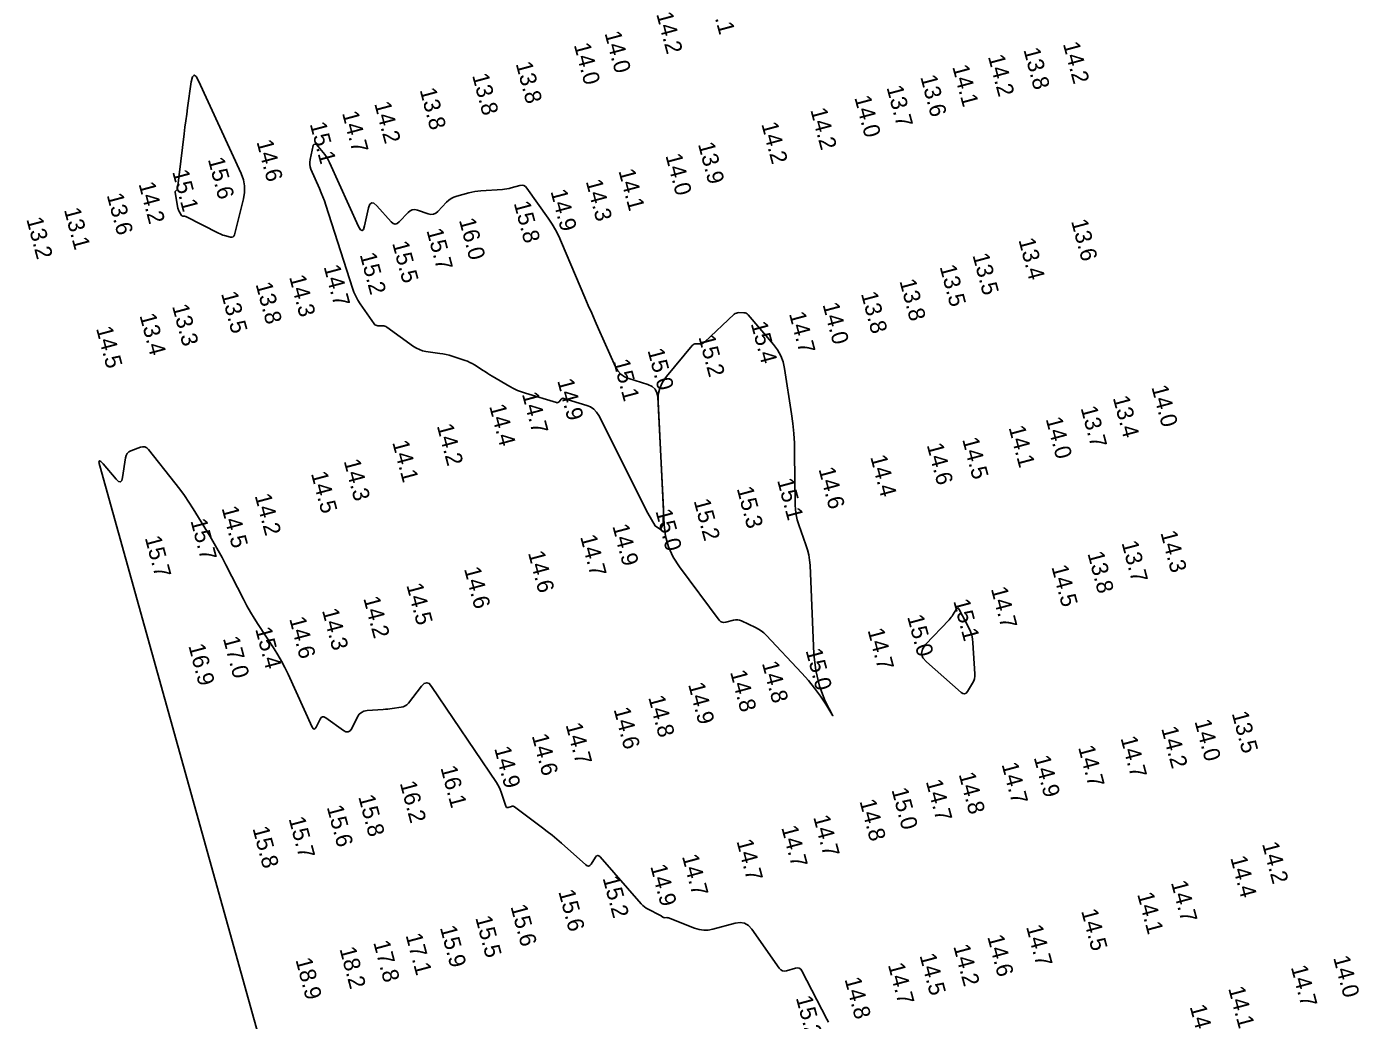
# Model space of a CAD drawing. Extents: x 988130 to 1132882, y 654656 to 841453.
# Drawn here: x 1052599.8 to 1053005.8, y 747871.9 to 748174.6 of the extents above; entities that cross this region are included whole.
import ezdxf

# ---------------------------------------------------------------- set-up
doc = ezdxf.new("R2010")
doc.units = 0
doc.layers.add('V-TOPO-MAJR', color=7, linetype='Continuous')
doc.layers.add('V-TOPO-SOUN', color=7, linetype='Continuous')

msp = doc.modelspace()

# ---------------------------------------------------------------- linework, layer by layer
at = {"layer": 'V-TOPO-MAJR'}
for points in [[(1052645.06, 748124.32), (1052645.11, 748124.42), (1052645.19, 748124.52), (1052645.55, 748124.87), (1052645.63, 748124.97), (1052645.69, 748125.07), (1052645.73, 748125.18), (1052645.76, 748125.3), (1052647.76, 748141.94), (1052648, 748143.92), (1052648.25, 748145.9), (1052648.52, 748147.87), (1052648.8, 748149.85), (1052649.93, 748157.75), (1052650.28, 748159.25), (1052650.77, 748159.81), (1052651.39, 748159.42), (1052652.16, 748158.08), (1052665.14, 748129.82), (1052665.83, 748127.95), (1052666.17, 748126.04), (1052666.18, 748124.1), (1052665.84, 748122.13), (1052663.05, 748111.14), (1052662.88, 748110.75), (1052662.64, 748110.5), (1052662.31, 748110.41), (1052661.89, 748110.46), (1052660.04, 748110.96), (1052659.58, 748111.09), (1052659.13, 748111.25), (1052658.69, 748111.43), (1052658.26, 748111.64), (1052648.24, 748116.7), (1052648.13, 748116.75), (1052648.03, 748116.79), (1052647.91, 748116.81), (1052647.8, 748116.82), (1052647.33, 748116.84), (1052647.22, 748116.86), (1052647.13, 748116.9), (1052647.04, 748116.96), (1052646.98, 748117.05), (1052646.25, 748118.25), (1052646.12, 748118.49), (1052646.01, 748118.73), (1052645.93, 748118.99), (1052645.87, 748119.25), (1052645.05, 748124.09), (1052645.04, 748124.21)], [(1052687.15, 748138.6), (1052687.22, 748138.66), (1052687.32, 748138.7), (1052687.74, 748138.81), (1052687.84, 748138.83), (1052687.93, 748138.81), (1052688.02, 748138.77), (1052688.09, 748138.7), (1052690.59, 748135.59), (1052691.01, 748135.03), (1052691.39, 748134.45), (1052691.74, 748133.84), (1052692.05, 748133.21), (1052700.91, 748113.68), (1052701.46, 748112.73), (1052701.94, 748112.44), (1052702.36, 748112.82), (1052702.7, 748113.86), (1052703.95, 748119.39), (1052704.34, 748120.46), (1052704.88, 748120.92), (1052705.58, 748120.77), (1052706.43, 748120.02), (1052710.77, 748115.12), (1052711.4, 748114.59), (1052712.03, 748114.41), (1052712.66, 748114.58), (1052713.3, 748115.1), (1052715.95, 748117.97), (1052716.57, 748118.5), (1052717.26, 748118.8), (1052718, 748118.86), (1052718.81, 748118.7), (1052722.14, 748117.56), (1052722.94, 748117.4), (1052723.69, 748117.46), (1052724.38, 748117.75), (1052725.02, 748118.26), (1052727.72, 748121.06), (1052728.4, 748121.68), (1052729.15, 748122.2), (1052729.96, 748122.61), (1052730.84, 748122.91), (1052734.47, 748123.92), (1052735.38, 748124.15), (1052736.3, 748124.33), (1052737.23, 748124.46), (1052738.17, 748124.55), (1052744.72, 748125.01), (1052745.4, 748125.08), (1052746.08, 748125.17), (1052746.75, 748125.3), (1052747.42, 748125.46), (1052750.07, 748126.18), (1052750.7, 748126.26), (1052751.27, 748126.16), (1052751.76, 748125.88), (1052752.19, 748125.41), (1052758.68, 748116.19), (1052759.84, 748114.44), (1052760.91, 748112.63), (1052761.88, 748110.77), (1052762.75, 748108.86), (1052769.87, 748092.06), (1052770.89, 748089.67), (1052771.92, 748087.28), (1052772.97, 748084.89), (1052774.03, 748082.51), (1052779.18, 748070.99), (1052779.9, 748069.73), (1052780.82, 748068.7), (1052781.95, 748067.91), (1052783.28, 748067.35), (1052789.03, 748065.58), (1052790.3, 748065), (1052791.23, 748064.16), (1052791.81, 748063.05), (1052792.06, 748061.68), (1052793.75, 748027.64), (1052793.67, 748023.09), (1052792.85, 748021.36), (1052791.29, 748022.46), (1052788.99, 748026.39), (1052774.1, 748056.09), (1052773.43, 748057.16), (1052772.59, 748058.04), (1052771.59, 748058.71), (1052770.43, 748059.19), (1052763.41, 748061.33), (1052763.18, 748061.37), (1052762.97, 748061.34), (1052762.78, 748061.25), (1052762.62, 748061.09), (1052761.99, 748060.31), (1052761.82, 748060.15), (1052761.64, 748060.05), (1052761.43, 748060.02), (1052761.2, 748060.06), (1052751.73, 748062.88), (1052750.49, 748063.29), (1052749.29, 748063.77), (1052748.11, 748064.33), (1052746.97, 748064.96), (1052741.6, 748068.14), (1052740.91, 748068.55), (1052740.23, 748068.96), (1052739.55, 748069.39), (1052738.88, 748069.81), (1052736.2, 748071.54), (1052735.52, 748071.95), (1052734.81, 748072.31), (1052734.09, 748072.63), (1052733.34, 748072.9), (1052729.38, 748074.19), (1052728.46, 748074.46), (1052727.54, 748074.7), (1052726.6, 748074.9), (1052725.66, 748075.05), (1052721.4, 748075.66), (1052720.4, 748075.87), (1052719.44, 748076.18), (1052718.53, 748076.62), (1052717.67, 748077.16), (1052709.52, 748083), (1052709.22, 748083.19), (1052708.9, 748083.32), (1052708.57, 748083.4), (1052708.21, 748083.43), (1052706.76, 748083.45), (1052706.42, 748083.49), (1052706.12, 748083.6), (1052705.85, 748083.79), (1052705.63, 748084.05), (1052701.39, 748090.14), (1052700.66, 748091.28), (1052700.02, 748092.46), (1052699.47, 748093.69), (1052699.01, 748094.96), (1052690.89, 748120.24), (1052690.46, 748121.51), (1052690, 748122.76), (1052689.51, 748124), (1052688.99, 748125.23), (1052686.39, 748131.15), (1052686.14, 748131.87), (1052686, 748132.6), (1052685.99, 748133.34), (1052686.1, 748134.09), (1052687.06, 748138.42), (1052687.09, 748138.52)], [(1052833.48, 748050.66), (1052833.67, 748047.65), (1052833.75, 748044.64), (1052833.89, 748029.01), (1052833.97, 748027.42), (1052834.19, 748025.85), (1052834.53, 748024.3), (1052835.01, 748022.77), (1052837.2, 748016.73), (1052837.68, 748015.2), (1052838.05, 748013.66), (1052838.3, 748012.08), (1052838.43, 748010.49), (1052839.63, 747983.37), (1052840.16, 747978.41), (1052841.3, 747973.63), (1052843.04, 747969.05), (1052845.39, 747964.65), (1052843.22, 747968.17), (1052841.59, 747970.67), (1052839.84, 747973.08), (1052837.97, 747975.39), (1052835.99, 747977.62), (1052825.09, 747989.21), (1052824.37, 747989.91), (1052823.59, 747990.53), (1052822.76, 747991.08), (1052821.87, 747991.55), (1052817.51, 747993.6), (1052816.94, 747993.81), (1052816.36, 747993.92), (1052815.76, 747993.91), (1052815.16, 747993.8), (1052812.74, 747993.12), (1052812.16, 747993.03), (1052811.64, 747993.12), (1052811.18, 747993.37), (1052810.77, 747993.79), (1052798.64, 748009.98), (1052796.73, 748012.93), (1052795.33, 748016.07), (1052794.41, 748019.38), (1052793.99, 748022.86), (1052792.12, 748060.37), (1052792.2, 748062.47), (1052792.66, 748064.44), (1052793.48, 748066.29), (1052794.68, 748068.01), (1052802.57, 748077.44), (1052802.8, 748077.67), (1052803.07, 748077.84), (1052803.37, 748077.94), (1052803.7, 748077.97), (1052805.07, 748077.98), (1052805.41, 748078.01), (1052805.72, 748078.1), (1052806, 748078.24), (1052806.27, 748078.45), (1052815.37, 748086.94), (1052815.67, 748087.17), (1052816, 748087.34), (1052816.35, 748087.43), (1052816.73, 748087.46), (1052818.3, 748087.44), (1052818.68, 748087.39), (1052819.02, 748087.28), (1052819.33, 748087.09), (1052819.6, 748086.83), (1052827.3, 748077.78), (1052828.53, 748076.12), (1052829.51, 748074.33), (1052830.22, 748072.42), (1052830.67, 748070.4), (1052832.78, 748056.65), (1052833.18, 748053.66)], [(1052883.44, 747997.43), (1052883.2, 747997.33), (1052882.95, 747997.03), (1052881.96, 747995.42), (1052881.7, 747995.02), (1052881.42, 747994.64), (1052881.12, 747994.27), (1052880.8, 747993.92), (1052873.63, 747986.32), (1052872.67, 747984.96), (1052872.39, 747983.62), (1052872.79, 747982.32), (1052873.88, 747981.05), (1052884.49, 747971.74), (1052885.03, 747971.39), (1052885.53, 747971.32), (1052885.99, 747971.53), (1052886.4, 747972.04), (1052887.97, 747974.61), (1052888.3, 747975.27), (1052888.53, 747975.95), (1052888.65, 747976.67), (1052888.66, 747977.4), (1052888.08, 747986.86), (1052887.95, 747988.05), (1052887.69, 747989.2), (1052887.31, 747990.32), (1052886.81, 747991.41), (1052883.89, 747997), (1052883.67, 747997.32)]]:
    msp.add_lwpolyline(points, close=True, dxfattribs=at)
msp.add_lwpolyline([(1052844.1, 747871.35), (1052843.54, 747872.24), (1052835.99, 747886.95), (1052835.62, 747887.48), (1052835.16, 747887.8), (1052834.61, 747887.9), (1052833.97, 747887.8), (1052831.24, 747886.97), (1052830.59, 747886.87), (1052830.01, 747886.96), (1052829.5, 747887.24), (1052829.06, 747887.73), (1052820.71, 747899.66), (1052819.67, 747900.79), (1052818.48, 747901.48), (1052817.13, 747901.71), (1052815.61, 747901.49), (1052808.87, 747899.62), (1052807.45, 747899.34), (1052806.05, 747899.3), (1052804.66, 747899.49), (1052803.29, 747899.91), (1052795.34, 747903.05), (1052795.2, 747903.1), (1052795.06, 747903.13), (1052794.91, 747903.15), (1052794.76, 747903.16), (1052794.14, 747903.14), (1052794, 747903.15), (1052793.87, 747903.18), (1052793.74, 747903.23), (1052793.63, 747903.3), (1052793.16, 747903.63), (1052793.05, 747903.71), (1052792.93, 747903.78), (1052792.8, 747903.85), (1052792.68, 747903.92), (1052789.17, 747905.69), (1052788.56, 747906.03), (1052788, 747906.43), (1052787.48, 747906.88), (1052786.99, 747907.38), (1052774.54, 747921.67), (1052774.14, 747922.02), (1052773.76, 747922.11), (1052773.4, 747921.96), (1052773.05, 747921.56), (1052771.71, 747919.45), (1052771.36, 747919.04), (1052770.97, 747918.87), (1052770.55, 747918.93), (1052770.1, 747919.23), (1052762.67, 747925.84), (1052761.27, 747927.06), (1052759.84, 747928.25), (1052758.39, 747929.41), (1052756.92, 747930.54), (1052748.43, 747936.9), (1052748.21, 747937.03), (1052747.97, 747937.1), (1052747.73, 747937.12), (1052747.47, 747937.06), (1052746.43, 747936.74), (1052746.19, 747936.7), (1052746, 747936.75), (1052745.85, 747936.88), (1052745.74, 747937.1), (1052744.35, 747941.37), (1052744.07, 747942.16), (1052743.73, 747942.92), (1052743.34, 747943.65), (1052742.9, 747944.36), (1052723.16, 747973.6), (1052722.42, 747974.43), (1052721.65, 747974.72), (1052720.87, 747974.48), (1052720.07, 747973.7), (1052716.06, 747968.52), (1052715.61, 747968.03), (1052715.09, 747967.65), (1052714.51, 747967.39), (1052713.86, 747967.24), (1052711.13, 747966.85), (1052710.45, 747966.76), (1052709.77, 747966.68), (1052709.08, 747966.61), (1052708.39, 747966.56), (1052703.46, 747966.23), (1052702.53, 747966.06), (1052701.75, 747965.69), (1052701.09, 747965.11), (1052700.58, 747964.32), (1052698.79, 747960.76), (1052698.3, 747960.05), (1052697.72, 747959.71), (1052697.04, 747959.74), (1052696.28, 747960.14), (1052690.87, 747964.06), (1052690.35, 747964.33), (1052689.89, 747964.35), (1052689.49, 747964.12), (1052689.15, 747963.64), (1052687.94, 747961.2), (1052687.63, 747960.74), (1052687.34, 747960.6), (1052687.05, 747960.75), (1052686.76, 747961.22), (1052679.4, 747977.34), (1052678.45, 747979.33), (1052677.42, 747981.28), (1052676.31, 747983.2), (1052675.13, 747985.07), (1052670.27, 747992.47), (1052669.08, 747994.34), (1052667.94, 747996.23), (1052666.85, 747998.16), (1052665.82, 748000.12), (1052660.43, 748010.66), (1052659.29, 748012.84), (1052658.11, 748015), (1052656.89, 748017.13), (1052655.63, 748019.24), (1052650.45, 748027.71), (1052649.16, 748029.75), (1052647.81, 748031.75), (1052646.39, 748033.71), (1052644.92, 748035.62), (1052636.84, 748045.77), (1052636.33, 748046.26), (1052635.76, 748046.54), (1052635.12, 748046.59), (1052634.43, 748046.43), (1052631.54, 748045.34), (1052630.89, 748045.01), (1052630.39, 748044.55), (1052630.05, 748043.97), (1052629.87, 748043.27), (1052629, 748037.27), (1052628.74, 748036.29), (1052628.32, 748035.87), (1052627.75, 748036.01), (1052627.01, 748036.7), (1052623.1, 748041.36), (1052622.34, 748042.15), (1052621.91, 748042.32), (1052621.8, 748041.87), (1052622.03, 748040.8), (1052727.97, 747660.65)], dxfattribs=at)

# ---------------------------------------------------------------- texts
at = {"layer": 'V-TOPO-SOUN'}
for s, p in [('14.1 ', (1052807.53, 748184.38)), ('14.2 ', (1052791.55, 748178.44)), ('14.0 ', (1052766.45, 748169.02)), ('14.0 ', (1052775.8, 748172.58)), ('14.2 ', (1052915.46, 748169.34)), ('14.2 ', (1052892.62, 748165.46)), ('13.8 ', (1052903.43, 748167.55)), ('13.8 ', (1052748.74, 748163.29)), ('14.1 ', (1052881.75, 748162.36)), ('13.8 ', (1052735.46, 748159.73)), ('13.6 ', (1052872.01, 748159.26)), ('13.8 ', (1052719.48, 748155.3)), ('14.0 ', (1052851.92, 748152.97)), ('13.7 ', (1052861.71, 748156.06)), ('14.2 ', (1052705.64, 748151.14)), ('14.2 ', (1052838.51, 748149.21)), ('15.1 ', (1052685.99, 748144.93)), ('14.7 ', (1052695.82, 748148.26)), ('14.2 ', (1052823.57, 748144.92)), ('14.6 ', (1052669.76, 748139.51)), ('13.9 ', (1052804.27, 748138.77)), ('15.6 ', (1052654.94, 748134.16)), ('14.0 ', (1052794.35, 748135.3)), ('15.1 ', (1052644.08, 748130.4)), ('14.1 ', (1052780.04, 748130.65)), ('14.2 ', (1052633.83, 748126.67)), ('14.9 ', (1052759.33, 748124.41)), ('14.3 ', (1052770.08, 748127.45)), ('13.6 ', (1052624.13, 748123.25)), ('15.8 ', (1052748.14, 748120.81)), ('13.1 ', (1052611.1, 748118.8)), ('13.2 ', (1052599.63, 748115.92)), ('15.7 ', (1052721.54, 748112.5)), ('16.0 ', (1052731.44, 748115.66)), ('13.6 ', (1052917.95, 748115.3)), ('15.5 ', (1052711.1, 748108.63)), ('13.4 ', (1052901.91, 748109.59)), ('15.2 ', (1052701.22, 748105.12)), ('13.5 ', (1052887.9, 748104.95)), ('14.7 ', (1052690.22, 748101.43)), ('13.5 ', (1052877.9, 748101.44)), ('13.8 ', (1052669.49, 748096.12)), ('14.3 ', (1052679.7, 748098.32)), ('13.8 ', (1052865.65, 748097.07)), ('13.5 ', (1052658.98, 748093.27)), ('13.8 ', (1052853.93, 748093.23)), ('13.3 ', (1052644.05, 748089.41)), ('14.0 ', (1052842.22, 748089.93)), ('13.4 ', (1052634.12, 748086.59)), ('15.4 ', (1052820.36, 748084.12)), ('14.7 ', (1052832, 748087.13)), ('14.5 ', (1052620.88, 748082.65)), ('15.2 ', (1052804.42, 748080.04)), ('15.0 ', (1052788.89, 748075.96)), ('15.1 ', (1052778.43, 748072.66)), ('14.9 ', (1052761.38, 748066.74)), ('14.0 ', (1052942.42, 748064.76)), ('14.7 ', (1052750.63, 748062.67)), ('13.4 ', (1052930.66, 748061.52)), ('14.4 ', (1052740.66, 748058.96)), ('13.7 ', (1052920.85, 748058.41)), ('14.2 ', (1052724.7, 748052.98)), ('14.1 ', (1052898.92, 748052.44)), ('14.0 ', (1052910.21, 748055.06)), ('14.1 ', (1052711.12, 748047.94)), ('14.6 ', (1052873.97, 748047.12)), ('14.5 ', (1052884.77, 748048.85)), ('14.4 ', (1052856.76, 748043.5)), ('14.3 ', (1052696.34, 748042.24)), ('14.6 ', (1052840.99, 748039.78)), ('14.5 ', (1052686.36, 748038.45)), ('15.1 ', (1052828.38, 748036.39)), ('14.2 ', (1052669.22, 748031.7)), ('15.3 ', (1052816.08, 748033.87)), ('14.5 ', (1052659.13, 748027.91)), ('15.0 ', (1052791.32, 748026.98)), ('15.2 ', (1052802.96, 748030.13)), ('15.7 ', (1052649.63, 748024.08)), ('15.7 ', (1052635.73, 748018.85)), ('14.7 ', (1052768.37, 748019.19)), ('14.9 ', (1052778.18, 748022.45)), ('14.3 ', (1052945.17, 748020.42)), ('13.7 ', (1052933.31, 748017.36)), ('14.6 ', (1052752.48, 748014.27)), ('13.8 ', (1052922.94, 748014.09)), ('14.6 ', (1052732.99, 748009.4)), ('14.5 ', (1052911.95, 748009.99)), ('14.5 ', (1052715.42, 748004.44)), ('14.7 ', (1052893.51, 748003.33)), ('14.2 ', (1052702.3, 748000.43)), ('15.1 ', (1052882.05, 747999.61)), ('14.3 ', (1052689.72, 747996.74)), ('15.0 ', (1052868, 747994.83)), ('15.4 ', (1052669.36, 747991.07)), ('14.6 ', (1052679.73, 747994.2)), ('14.7 ', (1052855.94, 747990.72)), ('17.0 ', (1052659.54, 747988.21)), ('16.9 ', (1052649, 747985.97)), ('15.0 ', (1052837.06, 747984.53)), ('14.8 ', (1052823.75, 747980.68)), ('14.9 ', (1052801.27, 747974.19)), ('14.8 ', (1052814.05, 747977.97)), ('14.8 ', (1052789.12, 747970.25)), ('14.6 ', (1052778.57, 747966.62)), ('14.7 ', (1052763.94, 747961.88)), ('14.0 ', (1052955.55, 747962.95)), ('13.5 ', (1052966.9, 747965.4)), ('14.6 ', (1052753.63, 747958.56)), ('14.7 ', (1052933.01, 747957.84)), ('14.2 ', (1052945.41, 747960.79)), ('14.9 ', (1052742.18, 747954.73)), ('14.7 ', (1052920.09, 747955.02)), ('14.7 ', (1052896.77, 747949.85)), ('14.9 ', (1052906.57, 747951.96)), ('16.1 ', (1052725.81, 747948.82)), ('14.8 ', (1052883.7, 747946.83)), ('16.2 ', (1052713.42, 747944.16)), ('15.0 ', (1052863.23, 747942.11)), ('14.7 ', (1052873.69, 747944.63)), ('15.8 ', (1052700.77, 747939.97)), ('14.8 ', (1052853.48, 747938.62)), ('15.6 ', (1052691.17, 747936.83)), ('14.7 ', (1052839.38, 747933.79)), ('15.8 ', (1052668.54, 747930.35)), ('15.7 ', (1052679.55, 747933.31)), ('14.7 ', (1052829.66, 747930.59)), ('14.7 ', (1052816, 747926.45)), ('14.2 ', (1052976.13, 747925.63)), ('14.7 ', (1052799.39, 747921.84)), ('14.4 ', (1052966.46, 747921.38)), ('14.9 ', (1052789.74, 747918.78)), ('15.2 ', (1052775.21, 747915.22)), ('14.7 ', (1052948.37, 747913.84)), ('15.6 ', (1052761.73, 747911.1)), ('14.1 ', (1052938.09, 747910.29)), ('15.6 ', (1052747.15, 747906.55)), ('14.5 ', (1052921.01, 747905.2)), ('15.5 ', (1052736.42, 747903.12)), ('17.1 ', (1052715.18, 747897.79)), ('15.9 ', (1052725.65, 747900.12)), ('14.6 ', (1052892.41, 747897.33)), ('14.7 ', (1052904.23, 747900.37)), ('18.2 ', (1052695.04, 747893.65)), ('17.8 ', (1052705.34, 747895.6)), ('14.2 ', (1052882.06, 747894.42)), ('18.9 ', (1052681.64, 747890.31)), ('14.7 ', (1052862.14, 747888.77)), ('14.5 ', (1052871.77, 747891.63)), ('14.0 ', (1052997.8, 747890.96)), ('14.7 ', (1052984.91, 747888.06)), ('14.8 ', (1052848.92, 747884.41)), ('14.1 ', (1052965.82, 747881.61)), ('15.2 ', (1052834.09, 747878.75)), ('14.1 ', (1052954.09, 747876.05))]:
    msp.add_text(s, height=5, rotation=285, dxfattribs=at).set_placement(p)

doc.saveas('drawing.dxf')
